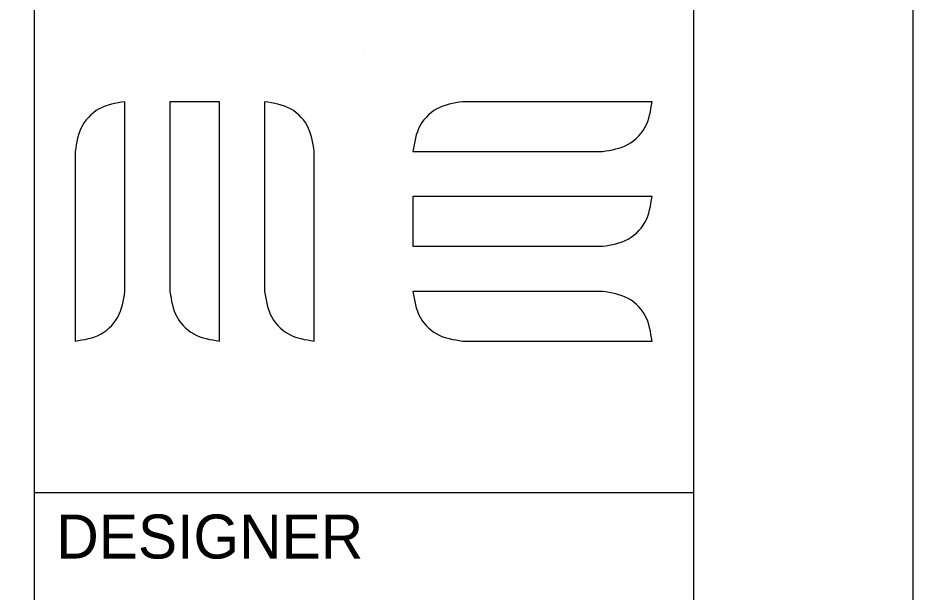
# Model space of a CAD drawing. Extents: x 0 to 34, y 0 to 30.1.
# Drawn here: x 31.963 to 34, y 2.774 to 4.079 of the extents above; entities that cross this region are included whole.
import ezdxf

# ---------------------------------------------------------------- set-up
doc = ezdxf.new("R2010")
doc.units = 0
for name, color, linetype in [('G-BRDR_LOGO', 7, 'Continuous'), ('SH_Border', 7, 'Continuous'), ('SH_Cut_Line', 7, 'Continuous'), ('SH_Data', 7, 'Continuous')]:
    doc.layers.add(name, color=color, linetype=linetype)

msp = doc.modelspace()

# ---------------------------------------------------------------- linework, layer by layer
at = {"layer": 'G-BRDR_LOGO'}
for points in [[(32.2061, 3.8887), (32.1984, 3.8875), (32.1907, 3.8862), (32.1831, 3.8847), (32.1756, 3.883), (32.1683, 3.881), (32.1611, 3.8786), (32.154, 3.8758), (32.1472, 3.8723), (32.1406, 3.8683), (32.1344, 3.8637), (32.1284, 3.8587), (32.1229, 3.8531), (32.1179, 3.8472), (32.1133, 3.841), (32.1093, 3.8344), (32.1058, 3.8276), (32.103, 3.8205), (32.1006, 3.8133), (32.0985, 3.8059), (32.0968, 3.7984), (32.0954, 3.7909), (32.0941, 3.7832), (32.0929, 3.7755), (32.0929, 3.3444), (32.1006, 3.3456), (32.1082, 3.3469), (32.1158, 3.3483), (32.1233, 3.35), (32.1307, 3.352), (32.1379, 3.3544), (32.1449, 3.3573), (32.1517, 3.3608), (32.1583, 3.3648), (32.1646, 3.3693), (32.1705, 3.3744), (32.176, 3.3799), (32.1811, 3.3859), (32.1856, 3.3921), (32.1897, 3.3987), (32.1931, 3.4055), (32.196, 3.4125), (32.1984, 3.4198), (32.2004, 3.4271), (32.2021, 3.4346), (32.2035, 3.4422), (32.2048, 3.4499), (32.2061, 3.4575), (32.2061, 3.8887)], [(32.4216, 3.8887), (32.3085, 3.8887), (32.3085, 3.4575), (32.3097, 3.4499), (32.311, 3.4422), (32.3124, 3.4346), (32.3141, 3.4271), (32.3161, 3.4198), (32.3185, 3.4125), (32.3214, 3.4055), (32.3249, 3.3987), (32.3289, 3.3921), (32.3334, 3.3859), (32.3385, 3.3799), (32.344, 3.3744), (32.35, 3.3693), (32.3562, 3.3648), (32.3628, 3.3608), (32.3696, 3.3573), (32.3766, 3.3544), (32.3839, 3.352), (32.3912, 3.35), (32.3987, 3.3483), (32.4063, 3.3469), (32.414, 3.3456), (32.4216, 3.3444), (32.4216, 3.8887)], [(32.6372, 3.7755), (32.636, 3.7832), (32.6347, 3.7909), (32.6333, 3.7984), (32.6316, 3.8059), (32.6296, 3.8133), (32.6271, 3.8205), (32.6243, 3.8276), (32.6208, 3.8344), (32.6168, 3.841), (32.6122, 3.8472), (32.6072, 3.8531), (32.6017, 3.8587), (32.5957, 3.8637), (32.5895, 3.8683), (32.5829, 3.8723), (32.5761, 3.8758), (32.569, 3.8786), (32.5618, 3.881), (32.5545, 3.883), (32.547, 3.8847), (32.5394, 3.8862), (32.5317, 3.8875), (32.524, 3.8887), (32.524, 3.4575), (32.5253, 3.4499), (32.5266, 3.4422), (32.528, 3.4346), (32.5297, 3.4271), (32.5317, 3.4198), (32.5341, 3.4125), (32.537, 3.4055), (32.5404, 3.3987), (32.5445, 3.3921), (32.549, 3.3859), (32.5541, 3.3799), (32.5596, 3.3744), (32.5655, 3.3693), (32.5718, 3.3648), (32.5784, 3.3608), (32.5852, 3.3573), (32.5922, 3.3544), (32.5994, 3.352), (32.6068, 3.35), (32.6143, 3.3483), (32.6219, 3.3469), (32.6295, 3.3456), (32.6372, 3.3444), (32.6372, 3.7755)], [(33.381, 3.817), (33.3855, 3.8233), (33.3896, 3.8299), (33.393, 3.8367), (33.3959, 3.8437), (33.3983, 3.8509), (33.4003, 3.8583), (33.402, 3.8658), (33.4034, 3.8734), (33.4047, 3.881), (33.406, 3.8887), (32.9748, 3.8887), (32.9671, 3.8875), (32.9595, 3.8862), (32.9519, 3.8847), (32.9444, 3.883), (32.937, 3.881), (32.9298, 3.8786), (32.9228, 3.8758), (32.9159, 3.8723), (32.9094, 3.8683), (32.9031, 3.8637), (32.8972, 3.8587), (32.8917, 3.8531), (32.8866, 3.8472), (32.882, 3.841), (32.878, 3.8344), (32.8746, 3.8276), (32.8717, 3.8205), (32.8693, 3.8133), (32.8673, 3.8059), (32.8656, 3.7984), (32.8641, 3.7909), (32.8628, 3.7832), (32.8616, 3.7755), (33.2928, 3.7755), (33.3005, 3.7767), (33.3081, 3.778), (33.3157, 3.7795), (33.3232, 3.7812), (33.3306, 3.7832), (33.3378, 3.7856), (33.3448, 3.7885), (33.3516, 3.7919), (33.3582, 3.7959), (33.3645, 3.8005), (33.3704, 3.8056), (33.3759, 3.8111), (33.381, 3.817)], [(33.3959, 3.6281), (33.3983, 3.6353), (33.4003, 3.6427), (33.402, 3.6502), (33.4034, 3.6578), (33.4047, 3.6654), (33.406, 3.6731), (32.8616, 3.6731), (32.8616, 3.5599), (33.2928, 3.5599), (33.3005, 3.5612), (33.3081, 3.5625), (33.3157, 3.5639), (33.3232, 3.5656), (33.3306, 3.5676), (33.3378, 3.57), (33.3448, 3.5729), (33.3516, 3.5763), (33.3582, 3.5804), (33.3645, 3.5849), (33.3704, 3.59), (33.3759, 3.5955), (33.381, 3.6014), (33.3855, 3.6077), (33.3896, 3.6143), (33.393, 3.6211), (33.3959, 3.6281)], [(33.3983, 3.3821), (33.3959, 3.3894), (33.393, 3.3964), (33.3896, 3.4032), (33.3855, 3.4098), (33.381, 3.4161), (33.3759, 3.422), (33.3704, 3.4275), (33.3645, 3.4326), (33.3582, 3.4371), (33.3516, 3.4412), (33.3448, 3.4446), (33.3378, 3.4475), (33.3306, 3.4499), (33.3232, 3.4519), (33.3157, 3.4536), (33.3081, 3.455), (33.3005, 3.4563), (33.2928, 3.4575), (32.8616, 3.4575), (32.8628, 3.4499), (32.8641, 3.4422), (32.8656, 3.4346), (32.8673, 3.4271), (32.8693, 3.4198), (32.8717, 3.4125), (32.8746, 3.4055), (32.878, 3.3987), (32.882, 3.3921), (32.8866, 3.3859), (32.8917, 3.3799), (32.8972, 3.3744), (32.9031, 3.3693), (32.9094, 3.3648), (32.9159, 3.3608), (32.9228, 3.3573), (32.9298, 3.3544), (32.937, 3.352), (32.9444, 3.35), (32.9519, 3.3483), (32.9595, 3.3469), (32.9671, 3.3456), (32.9748, 3.3444), (33.406, 3.3444), (33.4047, 3.352), (33.4034, 3.3597), (33.402, 3.3673), (33.4003, 3.3748), (33.3983, 3.3821)]]:
    msp.add_lwpolyline(points, dxfattribs=at)
at = {"layer": 'SH_Border'}
for p, q in [((32, 0.5), (32, 21.5)), ((32, 3), (33.5, 3))]:
    msp.add_line(p, q, dxfattribs=at)
msp.add_lwpolyline([(1.5, 21.5), (33.5, 21.5), (33.5, 0.5), (1.5, 0.5)], close=True, dxfattribs=at)
at = {"layer": 'SH_Cut_Line'}
msp.add_lwpolyline([(0, 0), (34, 0), (34, 22), (0, 22)], close=True, dxfattribs=at)
at = {"layer": 'SH_Data'}
msp.add_line((32.75, 4), (32.75, 4), dxfattribs=at)
msp.add_line((32.75, 4), (32.75, 4), dxfattribs=at)

# ---------------------------------------------------------------- texts
msp.add_text('DESIGNER', height=0.1, dxfattribs=at).set_placement((32.05, 2.85))

doc.saveas('drawing.dxf')
